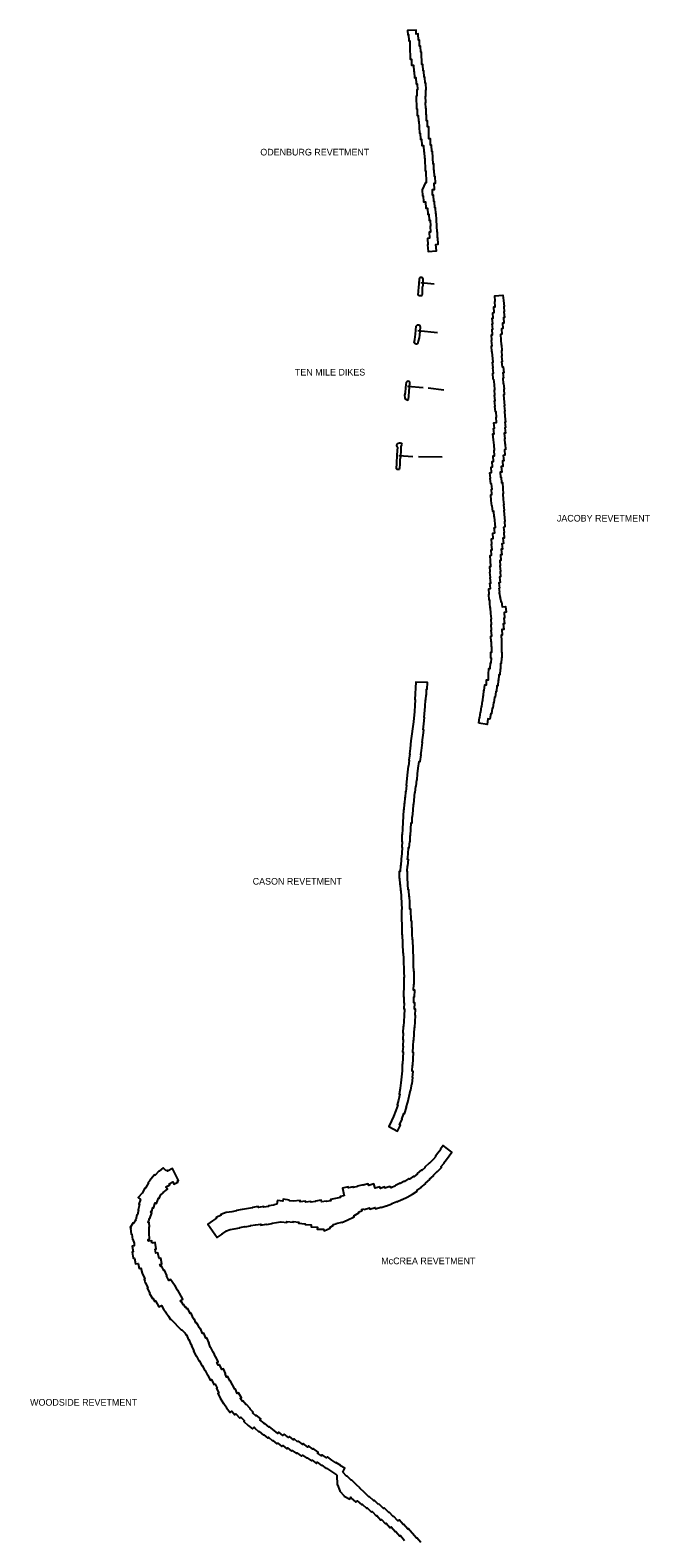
# Model space of a CAD drawing. Extents: x 2650582 to 3923188, y 277893 to 989177.
# Drawn here: x 3123847 to 3138714, y 850733 to 886887 of the extents above; entities that cross this region are included whole.
import ezdxf

# ---------------------------------------------------------------- set-up
doc = ezdxf.new("R2010")
doc.units = 0
doc.layers.add('Level 3', color=7, linetype='Continuous')

msp = doc.modelspace()

# ---------------------------------------------------------------- linework, layer by layer
at = {"layer": 'Level 3'}
for p, q in [((3133541, 880797), (3133223, 880829)), ((3133623, 879630), (3133145, 879676)), ((3133278, 878310), (3132901, 878343)), ((3133775, 878255), (3133396, 878299)), ((3133775, 878255), (3133396, 878299)), ((3133775, 878255), (3133396, 878299)), ((3133031, 876659), (3132695, 876677)), ((3133729, 876644), (3133164, 876659)), ((3133729, 876644), (3133164, 876659)), ((3133729, 876644), (3133164, 876659))]:
    msp.add_line(p, q, dxfattribs=at)
for points in [[(3133342, 885457), (3133348, 885457), (3133343, 885615), (3133324, 885615), (3133317, 885760), (3133299, 885759), (3133294, 885910), (3133273, 885910), (3133267, 886061), (3133246, 886060), (3133236, 886357), (3133219, 886356), (3133214, 886507), (3133189, 886506), (3133185, 886647), (3133161, 886647), (3133155, 886797), (3133111, 886795), (3133108, 886887), (3132901, 886880), (3132905, 886779), (3132927, 886780), (3132932, 886633), (3132955, 886634), (3132959, 886493), (3132954, 886493), (3132965, 886193), (3132993, 886194), (3132998, 886044), (3133043, 886046), (3133049, 885898), (3133058, 885899), (3133064, 885747), (3133102, 885748), (3133109, 885597), (3133131, 885598), (3133136, 885457), (3133125, 885454), (3133124, 885305)], [(3133124, 885305), (3133111, 885304), (3133119, 884997), (3133128, 884997), (3133133, 884842), (3133158, 884843), (3133163, 884701), (3133175, 884701), (3133184, 884419), (3133202, 884419), (3133208, 884269), (3133238, 884271), (3133243, 884119), (3133285, 884121), (3133290, 883968), (3133301, 883968), (3133306, 883816), (3133314, 883816), (3133326, 883513), (3133342, 883514), (3133351, 883226), (3133328, 883236), (3133254, 883059), (3133259, 882911), (3133274, 882911), (3133280, 882769), (3133331, 882771), (3133338, 882619), (3133381, 882621), (3133386, 882470), (3133411, 882471), (3133416, 882326), (3133447, 882327), (3133450, 882185), (3133444, 882185), (3133448, 882040), (3133419, 882039), (3133424, 881896), (3133378, 881893), (3133386, 881740), (3133381, 881740), (3133396, 881579), (3133597, 881599), (3133583, 881749), (3133634, 881752), (3133626, 881906), (3133622, 881906), (3133617, 882046), (3133608, 882046), (3133597, 882335), (3133593, 882335), (3133587, 882485), (3133580, 882484), (3133575, 882630), (3133555, 882629), (3133547, 882781), (3133528, 882780), (3133521, 882929), (3133503, 882928), (3133498, 883067), (3133545, 883068), (3133542, 883219), (3133572, 883220), (3133566, 883377), (3133547, 883376), (3133541, 883528), (3133535, 883528), (3133529, 883678), (3133513, 883677), (3133507, 883828), (3133504, 883828), (3133498, 883979), (3133483, 883979), (3133478, 884131), (3133454, 884130), (3133449, 884283), (3133412, 884281), (3133408, 884426), (3133415, 884426), (3133411, 884570), (3133381, 884569), (3133376, 884713), (3133359, 884713), (3133354, 884859), (3133349, 884859), (3133345, 885010), (3133337, 885009), (3133334, 885150), (3133338, 885150), (3133334, 885303), (3133341, 885303), (3133342, 885457)], [(3133192, 880954), (3133182, 880925), (3133172, 880807), (3133165, 880720), (3133158, 880633), (3133152, 880604), (3133147, 880560), (3133150, 880541), (3133175, 880527), (3133204, 880522), (3133238, 880523), (3133253, 880535)], [(3133253, 880535), (3133259, 880568), (3133263, 880725), (3133265, 880742), (3133274, 880773), (3133275, 880869), (3133276, 880913), (3133269, 880936), (3133251, 880955), (3133227, 880959), (3133212, 880959), (3133203, 880959), (3133192, 880954)], [(3134972, 878520), (3134958, 878519), (3134946, 878658), (3134963, 878660), (3134951, 878791), (3134953, 878791), (3134942, 878923), (3134954, 878924), (3134930, 879177), (3134924, 879176), (3134912, 879316), (3134929, 879318), (3134918, 879449), (3134924, 879450), (3134913, 879581), (3134943, 879584), (3134931, 879714), (3134945, 879716), (3134933, 879846), (3134946, 879848), (3134935, 879980), (3134955, 879982), (3134944, 880112), (3134982, 880116), (3134970, 880249), (3135004, 880252), (3134993, 880383), (3135007, 880385), (3134996, 880515), (3135189, 880532), (3135200, 880402), (3135207, 880402), (3135219, 880262), (3135208, 880261), (3135219, 880130), (3135213, 880129), (3135224, 879998), (3135204, 879995), (3135215, 879864), (3135178, 879861), (3135190, 879729), (3135154, 879726), (3135165, 879595), (3135133, 879591), (3135143, 879461), (3135139, 879460), (3135150, 879338), (3135154, 879338), (3135167, 879199), (3135152, 879197), (3135163, 879066), (3135159, 879066), (3135171, 878935), (3135159, 878933), (3135170, 878810), (3135195, 878812), (3135208, 878672), (3135191, 878671), (3135202, 878540)], [(3133139, 879355), (3133107, 879355), (3133079, 879375), (3133062, 879398), (3133078, 879467), (3133094, 879594), (3133108, 879788)], [(3133108, 879788), (3133124, 879805), (3133141, 879822), (3133168, 879822), (3133187, 879812), (3133199, 879785), (3133204, 879775), (3133186, 879575), (3133180, 879509), (3133159, 879432), (3133139, 879355)], [(3132866, 878445), (3132855, 878318), (3132843, 878194), (3132830, 878133), (3132834, 878070), (3132847, 878046), (3132873, 878027), (3132907, 878013), (3132921, 878032)], [(3132921, 878032), (3132928, 878120), (3132937, 878218), (3132947, 878335), (3132959, 878419), (3132954, 878444), (3132938, 878463), (3132913, 878469), (3132888, 878464), (3132866, 878445)], [(3134978, 876936), (3134965, 877066), (3134964, 877066), (3134951, 877205), (3134977, 877207), (3134965, 877338), (3134984, 877340), (3134973, 877472), (3135038, 877478), (3135027, 877609), (3135038, 877610), (3135028, 877732), (3135011, 877731), (3134999, 877870), (3135003, 877870), (3134991, 878000), (3135003, 878001), (3134991, 878133), (3134998, 878133), (3134987, 878265), (3134997, 878266), (3134986, 878389), (3134984, 878388), (3134972, 878520)], [(3135202, 878540), (3135189, 878538), (3135199, 878416), (3135206, 878416), (3135218, 878277), (3135209, 878276), (3135220, 878145), (3135205, 878143), (3135227, 877881), (3135222, 877881), (3135233, 877751), (3135227, 877750), (3135237, 877628), (3135239, 877628), (3135251, 877488), (3135237, 877487), (3135248, 877356), (3135237, 877354), (3135248, 877223), (3135221, 877220), (3135232, 877089), (3135226, 877089), (3135237, 876965), (3135241, 876966), (3135253, 876827)], [(3132771, 876961), (3132762, 876975), (3132735, 876985), (3132698, 876985), (3132665, 876977), (3132643, 876958), (3132638, 876930), (3132646, 876904), (3132664, 876885), (3132648, 876705), (3132638, 876495), (3132628, 876374), (3132646, 876361), (3132708, 876361)], [(3132708, 876361), (3132720, 876395), (3132726, 876472), (3132724, 876589), (3132737, 876664), (3132748, 876819), (3132747, 876917), (3132761, 876943), (3132771, 876961)], [(3134982, 874961), (3135008, 874963), (3134987, 875218), (3134980, 875218), (3134968, 875349), (3134945, 875347), (3134933, 875478), (3134922, 875477), (3134910, 875609), (3134908, 875608), (3134896, 875748), (3134927, 875751), (3134916, 875882), (3134930, 875884), (3134919, 876008), (3134896, 876006), (3134884, 876145), (3134890, 876146), (3134878, 876275), (3134916, 876278), (3134905, 876408), (3134942, 876412), (3134931, 876543), (3134964, 876546), (3134952, 876677), (3134990, 876681), (3134979, 876813), (3134989, 876814), (3134978, 876936)], [(3135253, 876827), (3135225, 876825), (3135236, 876694), (3135198, 876690), (3135209, 876559), (3135178, 876556), (3135189, 876425), (3135151, 876422), (3135163, 876290), (3135124, 876286), (3135135, 876166), (3135146, 876167), (3135159, 876035), (3135176, 876036), (3135186, 875897), (3135184, 875897), (3135195, 875765), (3135188, 875765), (3135199, 875632), (3135198, 875632), (3135209, 875501), (3135206, 875501), (3135217, 875369), (3135214, 875369), (3135235, 875107), (3135224, 875106), (3135235, 874974), (3135206, 874971)], [(3134878, 873154), (3134872, 873220), (3134860, 873219), (3134848, 873359), (3134860, 873360), (3134849, 873492), (3134889, 873496), (3134878, 873627), (3134896, 873629), (3134885, 873761), (3134889, 873761), (3134878, 873893), (3134884, 873894), (3134873, 874025), (3134902, 874028), (3134891, 874160), (3134894, 874160), (3134882, 874292), (3134915, 874295), (3134904, 874425), (3134930, 874428), (3134918, 874559), (3134926, 874560), (3134914, 874692), (3134956, 874695), (3134945, 874826), (3134993, 874830), (3134982, 874961)], [(3135206, 874971), (3135217, 874840), (3135212, 874840), (3135223, 874709), (3135189, 874706), (3135201, 874574), (3135164, 874571), (3135176, 874440), (3135149, 874438), (3135160, 874306), (3135128, 874304), (3135140, 874173), (3135112, 874170), (3135124, 874039), (3135118, 874038), (3135130, 873906), (3135122, 873905), (3135133, 873774), (3135109, 873772), (3135120, 873640), (3135092, 873637), (3135104, 873505), (3135092, 873504)], [(3135092, 873504), (3135104, 873408), (3135099, 873408), (3135102, 873381), (3135109, 873381), (3135117, 873294), (3135121, 873295), (3135125, 873251), (3135133, 873251), (3135140, 873177), (3135159, 873179), (3135169, 873060), (3135255, 873068), (3135267, 872928), (3135220, 872924), (3135231, 872790), (3135212, 872788), (3135224, 872653), (3135197, 872651), (3135208, 872516), (3135161, 872512), (3135172, 872378), (3135146, 872376), (3135158, 872241), (3135152, 872241), (3135154, 872109), (3135156, 872109), (3135159, 871974), (3135163, 871974), (3135165, 871834), (3135154, 871834), (3135149, 871698), (3135134, 871699), (3135129, 871564), (3135120, 871564), (3135115, 871429), (3135092, 871430), (3135087, 871295), (3135073, 871296), (3135068, 871161), (3135047, 871162), (3135036, 871026), (3135017, 871027), (3135005, 870893), (3134985, 870895), (3134973, 870760), (3134963, 870761), (3134944, 870627), (3134934, 870628), (3134915, 870494), (3134896, 870497), (3134878, 870363), (3134830, 870370), (3134811, 870236), (3134608, 870265)], [(3134608, 870265), (3134628, 870403), (3134636, 870402), (3134655, 870536), (3134658, 870535), (3134677, 870669), (3134680, 870669), (3134699, 870802), (3134704, 870802), (3134715, 870923), (3134723, 870923), (3134734, 871057), (3134743, 871056), (3134755, 871191), (3134795, 871187), (3134799, 871310), (3134841, 871309), (3134845, 871439), (3134843, 871439), (3134848, 871579), (3134885, 871578), (3134890, 871712), (3134911, 871712), (3134915, 871830), (3134899, 871830), (3134897, 871970), (3134922, 871970), (3134920, 872100), (3134915, 872100), (3134913, 872220), (3134910, 872220), (3134898, 872359), (3134921, 872361), (3134909, 872495), (3134917, 872496), (3134905, 872631), (3134915, 872632), (3134904, 872766), (3134914, 872767), (3134902, 872901), (3134903, 872901), (3134891, 873031), (3134886, 873030), (3134876, 873154), (3134878, 873154)], [(3133072, 868605), (3133084, 868604), (3133096, 868759), (3133109, 868758), (3133122, 868907), (3133128, 868906), (3133141, 869053), (3133159, 869186), (3133181, 869352), (3133203, 869349), (3133224, 869506), (3133217, 869507), (3133233, 869614), (3133256, 869807), (3133251, 869808), (3133292, 870103), (3133274, 870105), (3133294, 870251), (3133308, 870403), (3133303, 870403), (3133326, 870666), (3133333, 870827), (3133343, 870827), (3133347, 870950), (3133353, 870950), (3133358, 871083), (3133373, 871083), (3133380, 871240), (3133096, 871252), (3133079, 870835), (3133085, 870835), (3133079, 870687), (3133067, 870553), (3133067, 870552), (3133045, 870298), (3132983, 869843), (3132961, 869658), (3132944, 869537), (3132954, 869536), (3132935, 869383), (3132940, 869382), (3132921, 869240), (3132918, 869240), (3132898, 869097), (3132883, 868938), (3132882, 868931), (3132869, 868779), (3132874, 868779), (3132861, 868626), (3132856, 868627), (3132845, 868490)], [(3132845, 868490), (3132838, 868490), (3132827, 868341), (3132822, 868342), (3132813, 868191), (3132808, 868191), (3132799, 868038), (3132797, 868038), (3132791, 867888), (3132788, 867888), (3132783, 867737), (3132779, 867737), (3132771, 867589), (3132768, 867589), (3132768, 867430), (3132776, 867430), (3132767, 867293), (3132773, 867293), (3132767, 867145), (3132752, 867004), (3132743, 866859), (3132729, 866859), (3132722, 866711), (3132703, 866711), (3132704, 866554), (3132712, 866554), (3132717, 866403), (3132724, 866403), (3132729, 866256), (3132740, 866256), (3132746, 866101), (3132750, 866102), (3132761, 865802), (3132753, 865801)], [(3132987, 865517), (3132977, 865809), (3132959, 865809), (3132954, 865969), (3132949, 866109), (3132940, 866108), (3132934, 866271), (3132912, 866270), (3132906, 866411), (3132900, 866563), (3132899, 866712), (3132893, 866712), (3132899, 866846), (3132911, 866845), (3132921, 867000), (3132900, 867001), (3132914, 867130), (3132921, 867284), (3132943, 867282), (3132952, 867430), (3132962, 867430), (3132961, 867577), (3132970, 867576), (3132978, 867727), (3132981, 867727), (3132987, 867878), (3133009, 867877), (3133015, 868022), (3133023, 868021), (3133032, 868178), (3133041, 868324), (3133050, 868324), (3133072, 868605)], [(3132753, 865801), (3132767, 865204), (3132771, 865204), (3132786, 864765), (3132797, 864765), (3132801, 864610), (3132806, 864610), (3132811, 864306), (3132816, 864306), (3132817, 864168), (3132811, 864168), (3132809, 864014), (3132812, 864014), (3132808, 863709), (3132815, 863709), (3132813, 863565), (3132818, 863565), (3132813, 863418), (3132829, 863418), (3132822, 863250), (3132804, 862993), (3132799, 862993), (3132790, 862840), (3132798, 862840), (3132788, 862684), (3132794, 862684)], [(3133040, 862670), (3133053, 862669), (3133070, 862969), (3133073, 862969), (3133093, 863262), (3133081, 863263), (3133088, 863412), (3133068, 863413), (3133073, 863562), (3133050, 863563), (3133052, 863706), (3133071, 863705), (3133074, 863866), (3133047, 863867), (3133050, 864011), (3133057, 864010), (3133059, 864166), (3133062, 864166), (3133061, 864317), (3133049, 864317), (3133046, 864469), (3133041, 864616), (3133042, 864616), (3133027, 865073), (3133018, 865072), (3133014, 865214), (3133009, 865357), (3133004, 865357), (3133000, 865517), (3132987, 865517)], [(3132794, 862684), (3132786, 862527), (3132794, 862526), (3132784, 862385), (3132795, 862384), (3132779, 862090), (3132774, 862090), (3132769, 861932), (3132755, 861787), (3132741, 861643), (3132723, 861514), (3132722, 861507), (3132698, 861373), (3132716, 861369), (3132685, 861225), (3132651, 861114), (3132666, 861110), (3132618, 860979), (3132620, 860979), (3132565, 860839), (3132518, 860730), (3132450, 860597), (3132663, 860488), (3132734, 860625), (3132712, 860636), (3132776, 860771), (3132764, 860776), (3132816, 860908), (3132826, 860904), (3132879, 861050), (3132865, 861055), (3132905, 861184), (3132911, 861183), (3132942, 861322), (3132969, 861470), (3132978, 861468), (3133001, 861617), (3133011, 861616), (3133026, 861773), (3133023, 861773), (3133037, 861919), (3133015, 861921), (3133020, 862066), (3133026, 862066), (3133044, 862374), (3133029, 862375), (3133039, 862523), (3133034, 862523), (3133040, 862670)], [(3132770, 858843), (3132891, 858906), (3132892, 858905), (3133018, 858978), (3133128, 859050), (3133121, 859062), (3133231, 859137), (3133229, 859140), (3133335, 859224), (3133328, 859234), (3133432, 859322), (3133425, 859330), (3133523, 859412), (3133513, 859424), (3133614, 859515), (3133615, 859513), (3133715, 859613), (3133702, 859626), (3133783, 859714), (3133769, 859727), (3133838, 859807), (3133967, 859980), (3133754, 860139), (3133688, 860051), (3133697, 860044), (3133630, 859957), (3133568, 859886), (3133579, 859877), (3133513, 859805), (3133512, 859806), (3133425, 859717), (3133422, 859720), (3133315, 859622), (3133323, 859614), (3133243, 859544), (3133233, 859556), (3133132, 859472), (3133142, 859461), (3133050, 859392), (3133042, 859403), (3132945, 859334), (3132934, 859349), (3132830, 859281), (3132827, 859286), (3132728, 859228), (3132722, 859238), (3132609, 859179), (3132612, 859174)], [(3127111, 859534), (3127036, 859609), (3126940, 859522), (3126935, 859525), (3126843, 859431), (3126830, 859440), (3126739, 859334), (3126743, 859332), (3126711, 859282), (3126677, 859256), (3126686, 859244), (3126623, 859136), (3126618, 859137), (3126608, 859110), (3126598, 859115), (3126537, 859001), (3126535, 859002), (3126440, 858897), (3126494, 858849), (3126453, 858738), (3126473, 858730), (3126436, 858602), (3126448, 858598), (3126419, 858475), (3126407, 858478), (3126384, 858357), (3126377, 858346), (3126366, 858348), (3126363, 858325)], [(3126770, 857802), (3126764, 857858), (3126689, 857851), (3126688, 857858), (3126680, 857857), (3126677, 857891), (3126709, 857892), (3126704, 858038), (3126706, 858038), (3126702, 858189), (3126707, 858189), (3126704, 858296), (3126681, 858295), (3126688, 858332), (3126694, 858331), (3126707, 858394), (3126716, 858391), (3126764, 858523), (3126740, 858531), (3126756, 858578), (3126771, 858575), (3126786, 858646), (3126804, 858640), (3126849, 858764), (3126881, 858752), (3126926, 858876), (3126943, 858870), (3126973, 858953), (3127042, 859004), (3127035, 859013), (3127141, 859092), (3127105, 859140), (3127198, 859200), (3127184, 859222), (3127270, 859267), (3127298, 859214), (3127387, 859261), (3127373, 859285), (3127409, 859304), (3127259, 859587), (3127144, 859526), (3127133, 859546), (3127111, 859534)], [(3132612, 859174), (3132509, 859130), (3132502, 859147), (3132487, 859141), (3132479, 859162), (3132358, 859117), (3132347, 859148), (3132254, 859112), (3132240, 859153), (3132128, 859117), (3132093, 859223), (3131973, 859185), (3131959, 859225), (3131839, 859187), (3131835, 859200), (3131701, 859165), (3131702, 859159), (3131597, 859132), (3131593, 859149), (3131484, 859124), (3131479, 859148), (3131340, 859117), (3131381, 858937)], [(3130071, 858832), (3129917, 858851), (3129913, 858807), (3129781, 858826), (3129768, 858731), (3129690, 858718), (3129691, 858713), (3129563, 858691), (3129565, 858681), (3129457, 858662), (3129454, 858677), (3129324, 858656), (3129319, 858682), (3129181, 858658), (3129183, 858646), (3128938, 858605), (3128937, 858608), (3128799, 858584), (3128801, 858571), (3128684, 858551), (3128684, 858553), (3128554, 858531), (3128553, 858536), (3128420, 858488), (3128428, 858468), (3128313, 858413), (3128319, 858402), (3128221, 858334), (3128107, 858253), (3128337, 857935), (3128450, 858015), (3128449, 858017), (3128550, 858087), (3128547, 858091), (3128559, 858098), (3128642, 858128), (3128741, 858145), (3128742, 858140), (3128880, 858163), (3128878, 858176), (3128996, 858196), (3128996, 858194), (3129135, 858217), (3129134, 858223), (3129252, 858242), (3129254, 858236), (3129381, 858257), (3129385, 858231), (3129513, 858252), (3129514, 858246), (3129653, 858269), (3129651, 858279), (3129760, 858298), (3129851, 858314)], [(3131381, 858937), (3131286, 858916), (3131292, 858891), (3131055, 858845), (3131061, 858813), (3130957, 858796), (3130955, 858810), (3130835, 858792), (3130830, 858827), (3130695, 858810), (3130696, 858800), (3130585, 858786), (3130584, 858796), (3130458, 858780), (3130455, 858805), (3130328, 858789), (3130323, 858826), (3130159, 858805), (3130068, 858813), (3130071, 858832)], [(3131856, 858625), (3131861, 858608), (3131989, 858643), (3131998, 858612), (3132124, 858652), (3132135, 858619), (3132262, 858660), (3132265, 858652), (3132392, 858697), (3132394, 858691), (3132525, 858743), (3132522, 858749), (3132643, 858799), (3132646, 858792), (3132767, 858848), (3132770, 858843)], [(3126363, 858325), (3126333, 858279), (3126319, 858288), (3126246, 858172), (3126269, 858158), (3126252, 858156), (3126270, 858015), (3126286, 858017), (3126302, 857885), (3126313, 857886), (3126341, 857799), (3126345, 857757), (3126341, 857734), (3126296, 857727), (3126319, 857589), (3126293, 857585), (3126318, 857436), (3126349, 857441), (3126378, 857302), (3126437, 857314), (3126461, 857191), (3126499, 857199), (3126532, 857080), (3126593, 856962), (3126596, 856939), (3126583, 856933), (3126602, 856890), (3126607, 856847), (3126618, 856848), (3126668, 856727), (3126655, 856721), (3126715, 856597), (3126710, 856594), (3126780, 856475), (3126793, 856482), (3126835, 856404), (3126857, 856416), (3126936, 856271), (3126980, 856295), (3126982, 856292), (3126997, 856301), (3127053, 856200), (3127055, 856202)], [(3129851, 858314), (3129868, 858307), (3129869, 858311), (3130005, 858294), (3130007, 858316), (3130156, 858302), (3130158, 858316), (3130291, 858304), (3130289, 858275), (3130443, 858263), (3130442, 858243), (3130587, 858235), (3130585, 858188), (3130737, 858180), (3130736, 858137), (3130884, 858134), (3130898, 858098), (3131042, 858155), (3131036, 858171), (3131125, 858233), (3131114, 858249), (3131186, 858259), (3131185, 858269), (3131325, 858305), (3131328, 858297), (3131455, 858349), (3131620, 858434), (3131609, 858456), (3131735, 858529), (3131725, 858546), (3131810, 858584), (3131798, 858610), (3131856, 858625)], [(3127472, 856385), (3127457, 856428), (3127508, 856456), (3127388, 856676), (3127382, 856673), (3127317, 856794), (3127312, 856791), (3127215, 856927), (3127177, 856900), (3127118, 857017), (3127127, 857021), (3127070, 857149), (3127057, 857143), (3127002, 857252), (3126983, 857243), (3126959, 857291), (3127007, 857300), (3126980, 857437), (3126939, 857429), (3126909, 857570), (3126861, 857559), (3126845, 857659), (3126868, 857663), (3126844, 857814), (3126770, 857802)], [(3127055, 856202), (3127065, 856185), (3127070, 856187), (3127093, 856152), (3127103, 856126), (3127109, 856128), (3127164, 856045), (3127168, 856048), (3127213, 855972), (3127220, 855976), (3127481, 855713), (3127485, 855718), (3127559, 855650), (3127580, 855598), (3127595, 855604), (3127644, 855483), (3127654, 855487), (3127702, 855367), (3127712, 855371), (3127724, 855340), (3127722, 855340), (3127775, 855216), (3127770, 855213), (3127830, 855086), (3127835, 855089), (3127893, 854974), (3127907, 854980), (3127968, 854859), (3127975, 854862), (3128037, 854743), (3128045, 854748), (3128103, 854631)], [(3128391, 854887), (3128355, 854871), (3128326, 854935), (3128360, 854951), (3128298, 855077), (3128292, 855074), (3128242, 855185), (3128235, 855182), (3128182, 855301), (3128175, 855298), (3128133, 855401), (3128139, 855403), (3128086, 855533), (3128058, 855521), (3128010, 855642), (3127979, 855629), (3127930, 855750), (3127923, 855747), (3127909, 855780), (3127900, 855776), (3127864, 855864), (3127850, 855858), (3127834, 855895), (3127823, 855891), (3127809, 855929), (3127808, 855929), (3127789, 855974), (3127779, 855969), (3127764, 856003), (3127760, 856002), (3127708, 856120), (3127689, 856111), (3127674, 856149), (3127670, 856147), (3127629, 856235), (3127604, 856223), (3127584, 856271), (3127563, 856262), (3127533, 856326), (3127519, 856320), (3127488, 856392), (3127472, 856385)], [(3129469, 853466), (3129457, 853475), (3129462, 853481), (3129359, 853564), (3129379, 853589), (3129271, 853675), (3129261, 853662), (3129185, 853733), (3129194, 853743), (3129114, 853823), (3129124, 853832), (3129028, 853938), (3129021, 853932), (3128949, 854022), (3128934, 854010), (3128887, 854072), (3128918, 854091), (3128844, 854210), (3128814, 854191), (3128770, 854302), (3128761, 854299), (3128705, 854404), (3128700, 854402), (3128647, 854503), (3128640, 854499), (3128587, 854600), (3128556, 854584), (3128526, 854670), (3128536, 854674), (3128485, 854787), (3128443, 854768), (3128391, 854887)], [(3128103, 854631), (3128108, 854634), (3128168, 854512), (3128195, 854528), (3128256, 854409), (3128283, 854421), (3128334, 854326), (3128315, 854315), (3128371, 854208), (3128349, 854194), (3128408, 854088), (3128403, 854084), (3128486, 853956), (3128490, 853958), (3128562, 853852), (3128558, 853849), (3128642, 853735), (3128686, 853769), (3128756, 853682), (3128784, 853705), (3128874, 853606), (3128898, 853627), (3128988, 853537), (3128975, 853522), (3129076, 853429), (3129185, 853344), (3129219, 853387), (3129235, 853374)], [(3129235, 853374), (3129229, 853367), (3129335, 853278), (3129338, 853281), (3129446, 853195), (3129451, 853200), (3129547, 853122), (3129566, 853145), (3129665, 853063), (3129668, 853066), (3129769, 852986), (3129786, 853006), (3129887, 852925), (3129906, 852949), (3130008, 852868), (3130024, 852888), (3130117, 852810)], [(3130270, 853028), (3130179, 853104), (3130164, 853087), (3130066, 853164), (3130044, 853137), (3129940, 853219), (3129912, 853184), (3129812, 853264), (3129787, 853233), (3129585, 853399), (3129578, 853390), (3129474, 853473), (3129469, 853466)], [(3131345, 852309), (3131398, 852403), (3131295, 852460), (3131297, 852464), (3131184, 852538), (3131181, 852533), (3131085, 852598), (3131082, 852594), (3130977, 852672), (3130959, 852649), (3130854, 852723), (3130835, 852697), (3130739, 852767), (3130753, 852786), (3130639, 852873), (3130630, 852861), (3130528, 852936), (3130509, 852911), (3130400, 852993), (3130386, 852973), (3130285, 853048), (3130270, 853028)], [(3130117, 852810), (3130135, 852831), (3130237, 852754), (3130248, 852769), (3130355, 852690), (3130377, 852719), (3130482, 852642), (3130491, 852654), (3130595, 852576), (3130609, 852595), (3130713, 852519), (3130732, 852544), (3130838, 852469), (3130844, 852477), (3130949, 852399), (3130954, 852406), (3131169, 852261), (3131172, 852266)], [(3131172, 852266), (3131201, 852235), (3131214, 852002), (3131220, 852002), (3131279, 851858), (3131288, 851861), (3131278, 851849), (3131383, 851743), (3131377, 851731), (3131516, 851661), (3131540, 851709), (3131546, 851702), (3131540, 851696), (3131660, 851589), (3131690, 851624), (3131803, 851522), (3131816, 851537), (3131924, 851437), (3131935, 851449), (3132037, 851346)], [(3132207, 851532), (3132101, 851636), (3132089, 851624), (3131984, 851726), (3131976, 851718), (3131865, 851819), (3131869, 851822), (3131755, 851925), (3131758, 851929), (3131677, 852003), (3131556, 852124), (3131548, 852117), (3131444, 852222), (3131437, 852215), (3131345, 852309)], [(3133219, 850621), (3133124, 850734), (3133115, 850726), (3132918, 850955), (3132904, 850944), (3132806, 851059), (3132796, 851051), (3132698, 851162), (3132671, 851139), (3132568, 851254), (3132556, 851242), (3132457, 851350), (3132449, 851343), (3132343, 851454), (3132325, 851436), (3132218, 851543), (3132207, 851532)], [(3132037, 851346), (3132051, 851361), (3132154, 851256), (3132163, 851265), (3132264, 851158), (3132280, 851173), (3132375, 851068), (3132390, 851081), (3132487, 850971), (3132512, 850993), (3132609, 850878), (3132619, 850886), (3132717, 850775), (3132733, 850788), (3132829, 850673)]]:
    msp.add_lwpolyline(points, dxfattribs=at)

# ---------------------------------------------------------------- texts
for s, p in [('ODENBURG REVETMENT', (3129369, 883882)), ('TEN MILE DIKES', (3130198, 878605)), ('JACOBY REVETMENT', (3136484, 875103)), ('CASON REVETMENT', (3129186, 866397)), ('McCREA REVETMENT', (3132270, 857294)), ('WOODSIDE REVETMENT', (3123846, 853902))]:
    msp.add_text(s, height=160, dxfattribs=at).set_placement(p)

doc.saveas('drawing.dxf')
